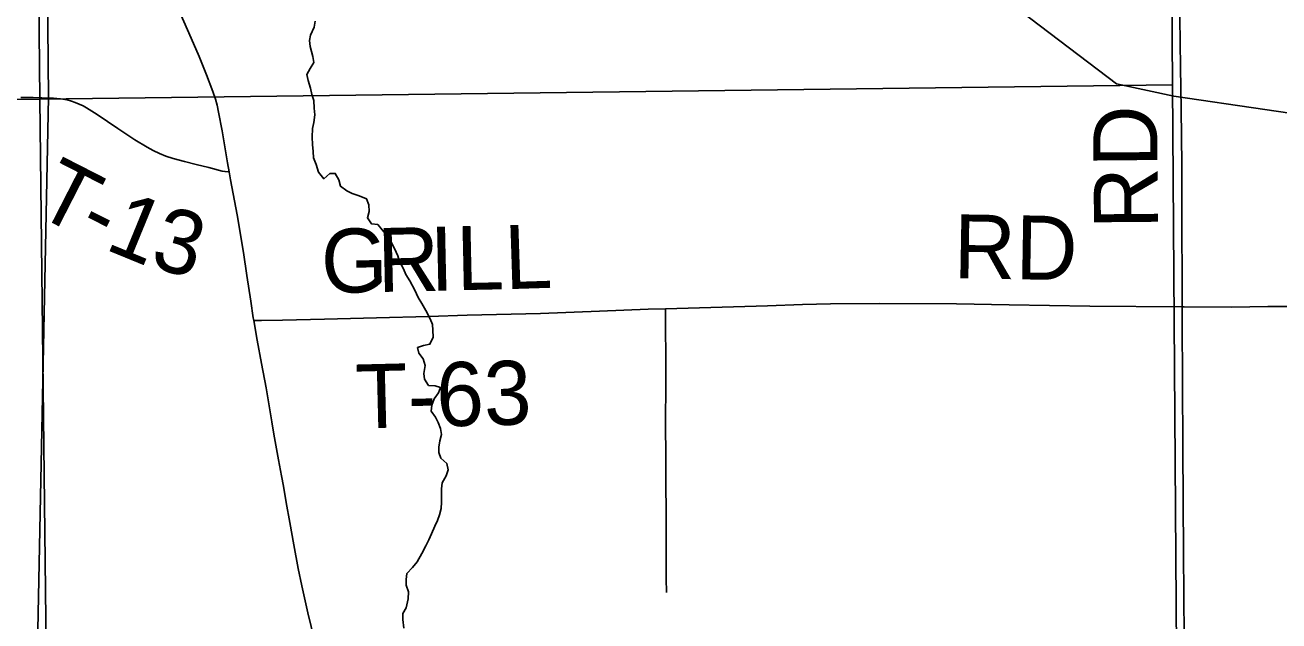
# Model space of a CAD drawing. Extents: x 0 to 34, y -5 to 22.
# Drawn here: x 4.121 to 5.234, y 15.13 to 15.66 of the extents above; entities that cross this region are included whole.
import ezdxf

# ---------------------------------------------------------------- set-up
doc = ezdxf.new("R2010")
doc.units = 0
for name, color, linetype in [('GM_X_Corporation', 7, 'Continuous'), ('GM_X_County_Road', 7, 'Continuous'), ('GM_X_County_Road_Text', 7, 'Continuous'), ('GM_X_Minor_River', 7, 'Continuous'), ('GM_X_Rail_Line', 7, 'Continuous'), ('GM_X_Section', 7, 'Continuous'), ('GM_X_Township_Road', 7, 'Continuous'), ('GM_X_Township_Road_Text', 7, 'Continuous')]:
    doc.layers.add(name, color=color, linetype=linetype)

msp = doc.modelspace()

# ---------------------------------------------------------------- linework, layer by layer
at = {"layer": 'GM_X_Corporation'}
msp.add_lwpolyline([(4.0447, 15.8182), (4.1399, 15.8168), (4.1417, 15.5953), (4.1319, 15.0927)], dxfattribs=at)
at = {"layer": 'GM_X_County_Road'}
for points in [[(5.1481, 15.4093), (5.148, 15.4361), (5.1478, 15.4766), (5.1478, 15.5357), (5.1472, 15.5849), (5.1465, 15.6221), (5.1459, 15.666), (5.1455, 15.703), (5.1454, 15.7299), (5.1443, 15.7983), (5.1439, 15.8386), (5.1434, 15.8728), (5.1431, 15.8894)], [(5.1559, 14.5996), (5.1554, 14.6402), (5.1547, 14.6837), (5.154, 14.7521), (5.1535, 14.7894), (5.1525, 14.8547), (5.152, 14.8982), (5.1519, 14.9231), (5.1517, 14.9573), (5.1513, 14.9884), (5.1509, 15.0195), (5.1498, 15.1159), (5.1492, 15.1905), (5.1486, 15.2838), (5.1484, 15.3429), (5.1481, 15.3958), (5.1481, 15.4093)]]:
    msp.add_lwpolyline(points, dxfattribs=at)
at = {"layer": 'GM_X_Minor_River'}
for points in [[(4.4854, 15.3114), (4.4815, 15.3167), (4.4822, 15.322), (4.484, 15.3277), (4.488, 15.3328), (4.4898, 15.3378), (4.4849, 15.3392), (4.4792, 15.3395), (4.4756, 15.3451), (4.4751, 15.35), (4.4761, 15.3573), (4.4745, 15.363), (4.4706, 15.3682), (4.4694, 15.3731), (4.4747, 15.3751), (4.4804, 15.376), (4.4833, 15.3825), (4.4828, 15.3886), (4.4827, 15.3936), (4.4807, 15.3985), (4.4767, 15.406), (4.4732, 15.4124), (4.47, 15.4177), (4.4669, 15.4241), (4.4625, 15.4324), (4.459, 15.438), (4.457, 15.4429), (4.4534, 15.4497), (4.4518, 15.4546), (4.449, 15.461), (4.4458, 15.4674), (4.4423, 15.4723), (4.438, 15.4776), (4.4341, 15.4824), (4.4284, 15.4831), (4.4249, 15.4884), (4.4263, 15.4941), (4.4262, 15.4998), (4.4242, 15.5051), (4.4177, 15.508), (4.4115, 15.5098), (4.4065, 15.5124), (4.4011, 15.5164), (4.3995, 15.5221), (4.3963, 15.5278), (4.3914, 15.5277), (4.3862, 15.523), (4.3815, 15.529), (4.3794, 15.5358), (4.377, 15.5415), (4.3766, 15.5472), (4.376, 15.5536), (4.3759, 15.5601), (4.3762, 15.5677), (4.3772, 15.5731), (4.3782, 15.5799), (4.3777, 15.5856), (4.3772, 15.5925), (4.3756, 15.5978), (4.3743, 15.6035), (4.3723, 15.6103), (4.371, 15.6156), (4.374, 15.621), (4.3773, 15.6263), (4.3764, 15.6317), (4.374, 15.6404), (4.3735, 15.6457), (4.3745, 15.6507), (4.3775, 15.6576), (4.3785, 15.6629)], [(4.4571, 15.124), (4.4562, 15.1316), (4.4564, 15.1369), (4.4594, 15.1419), (4.4611, 15.15), (4.4614, 15.1561), (4.4594, 15.1621), (4.4593, 15.1671), (4.4599, 15.1724), (4.4648, 15.1778), (4.4689, 15.1828), (4.4733, 15.1902), (4.4766, 15.1971), (4.4795, 15.2025), (4.4817, 15.2078), (4.4846, 15.2144), (4.4872, 15.2194), (4.489, 15.2247), (4.4904, 15.2301), (4.4907, 15.2358), (4.4905, 15.2476), (4.4911, 15.2529), (4.4948, 15.2591), (4.4966, 15.2644), (4.4953, 15.2701), (4.4899, 15.275), (4.4883, 15.2799), (4.4882, 15.2848), (4.4892, 15.2902), (4.4907, 15.2959), (4.4898, 15.3012), (4.4878, 15.3065), (4.4854, 15.3114)]]:
    msp.add_lwpolyline(points, dxfattribs=at)
at = {"layer": 'GM_X_Rail_Line'}
msp.add_lwpolyline([(4.2939, 16.5478), (4.428, 16.1111), (4.4985, 16.0565), (5.0896, 15.6072), (5.1407, 15.5965), (5.3829, 15.5608), (5.4458, 15.537), (5.4636, 15.5061), (5.4813, 15.3635), (5.5596, 14.8004), (5.5691, 14.7552), (5.5999, 14.7267)], dxfattribs=at)
at = {"layer": 'GM_X_Section'}
for points in [[(5.1327, 16.5549), (5.1393, 15.6065), (4.1342, 15.5936), (4.1248, 16.5469), (4.5534, 16.5511), (5.0529, 16.5543)], [(4.1248, 16.5469), (4.1342, 15.5936), (3.6228, 15.592), (3.1044, 15.6177), (3.0783, 16.5351), (3.1825, 16.5361), (3.5929, 16.5408), (3.9967, 16.5453)], [(3.1044, 15.6177), (3.6228, 15.592), (4.1342, 15.5936), (4.1458, 14.5934), (3.5359, 14.5917), (3.104, 14.6056)], [(4.1342, 15.5936), (5.1393, 15.6065), (5.1465, 14.6013), (4.1458, 14.5934)]]:
    msp.add_lwpolyline(points, close=True, dxfattribs=at)
at = {"layer": 'GM_X_Township_Road'}
for points in [[(4.3021, 15.5291), (4.3006, 15.5372), (4.2959, 15.5655), (4.2927, 15.5823), (4.2914, 15.5885), (4.2901, 15.5936), (4.2878, 15.6005), (4.2822, 15.6152), (4.2755, 15.6316), (4.2684, 15.648), (4.2554, 15.6774)], [(4.1173, 15.5952), (4.1233, 15.5952), (4.1281, 15.5952)], [(4.1281, 15.5952), (4.1358, 15.595), (4.1419, 15.5947)], [(4.1419, 15.5947), (4.1463, 15.5946), (4.1524, 15.594), (4.1585, 15.593), (4.1623, 15.5919), (4.1655, 15.5909), (4.1692, 15.5894), (4.1725, 15.5877), (4.1757, 15.5859), (4.1849, 15.58), (4.2033, 15.5676), (4.2186, 15.5575), (4.2294, 15.5511), (4.2346, 15.5482), (4.2405, 15.5454), (4.2459, 15.5432), (4.2525, 15.5411), (4.2625, 15.5384), (4.2728, 15.5358), (4.2842, 15.5329), (4.296, 15.5299), (4.2985, 15.5294), (4.3012, 15.5292), (4.3021, 15.5291)], [(4.324, 15.3971), (4.3236, 15.3995), (4.3213, 15.4144), (4.318, 15.4372), (4.3148, 15.4576), (4.3092, 15.4909), (4.3034, 15.522), (4.3021, 15.5291)], [(4.324, 15.3971), (4.3309, 15.3972), (4.3495, 15.3976), (4.3867, 15.3982), (4.4329, 15.3994), (4.4794, 15.4007), (4.5134, 15.4018), (4.5784, 15.4035), (4.6309, 15.4054), (4.6741, 15.4072), (4.6893, 15.4076)], [(4.6893, 15.4076), (4.78, 15.4103), (4.8109, 15.4114), (4.8358, 15.4119), (4.8794, 15.4124), (4.9478, 15.4121), (4.9944, 15.411), (5.0659, 15.41), (5.1481, 15.4093)], [(4.6902, 15.1555), (4.69, 15.1681), (4.6899, 15.2178), (4.6898, 15.2612), (4.6896, 15.283), (4.6895, 15.2985), (4.6896, 15.3482), (4.6893, 15.4076)], [(5.1481, 15.4093), (5.1499, 15.4093), (5.192, 15.4091), (5.2241, 15.4095), (5.2554, 15.4097), (5.2711, 15.4091), (5.2752, 15.4089), (5.2806, 15.4082), (5.2849, 15.4077), (5.2897, 15.4069), (5.3173, 15.4018), (5.3629, 15.3922), (5.4083, 15.3817), (5.4238, 15.3782)], [(4.3812, 15.0989), (4.3778, 15.1133), (4.372, 15.1374), (4.3666, 15.1616), (4.3634, 15.1768), (4.3596, 15.1979), (4.3561, 15.2177), (4.3529, 15.2354), (4.3503, 15.25), (4.3486, 15.2591), (4.3461, 15.2734), (4.3419, 15.2963), (4.3402, 15.3071), (4.3349, 15.3375), (4.3308, 15.3589), (4.327, 15.3797), (4.324, 15.3971)]]:
    msp.add_lwpolyline(points, dxfattribs=at)

# ---------------------------------------------------------------- texts
at = {"layer": 'GM_X_County_Road_Text'}
msp.add_text('RD', height=0.05682, rotation=90.4804, dxfattribs=at).set_placement((5.1266, 15.4786))
at = {"layer": 'GM_X_Township_Road_Text'}
for s, height, rotation, p in [('T', 0.0568, 332.906, (4.1273, 15.4929)), ('1', 0.0568, 337.7226, (4.1907, 15.4609)), ('-', 0.0568, 333.2331, (4.1655, 15.4734)), ('3', 0.0568, 344.9597, (4.2305, 15.4451)), ('RD', 0.05682, 359.0529, (4.9449, 15.4347)), ('G', 0.0568, 1.235, (4.3843, 15.4214)), ('R', 0.0568, 1.2374, (4.4343, 15.4224)), ('I', 0.0568, 1.2335, (4.4809, 15.4235)), ('L', 0.0568, 1.2572, (4.5043, 15.424)), ('L', 0.0568, 1.8527, (4.5474, 15.4249)), ('T-63', 0.05682, 1.4037, (4.4149, 15.3012))]:
    msp.add_text(s, height=height, rotation=rotation, dxfattribs=at).set_placement(p)

doc.saveas('drawing.dxf')
